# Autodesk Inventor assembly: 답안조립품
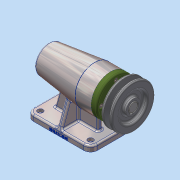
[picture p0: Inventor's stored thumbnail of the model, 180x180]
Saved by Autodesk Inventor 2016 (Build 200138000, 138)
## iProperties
Created: 2018-09
Part Number: 답안조립품
Material: 일반
Document SubType Name: Assembly
Designer: 605-17
Author: 605-17
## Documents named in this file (12)
- C:\Users\605-17\Desktop\480907v1006\답안조립품.iam
- C:\Users\605-17\Desktop\480907v1006\본체.ipt
- C:\Users\605-17\Desktop\480907v1006\축.ipt
- C:\Users\605-17\Desktop\480907v1006\베어링 6004.ipt
- C:\Users\605-17\Desktop\480907v1006\어댑터슬리브.ipt
- C:\Users\605-17\Desktop\480907v1006\베어링 51202.ipt
- C:\Users\605-17\Desktop\480907v1006\볼트 M4.ipt
- C:\Users\605-17\Desktop\480907v1006\키 5 x 5 x 16.ipt
- C:\Users\605-17\Desktop\480907v1006\커버.ipt
- C:\Users\605-17\Desktop\480907v1006\오일 실.ipt
- C:\Users\605-17\Desktop\480907v1006\V벨트풀리.ipt
- C:\Users\605-17\Desktop\480907v1006\멈춤나사 M3.ipt
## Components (1 placed, 1 different names)
1. V벨트풀리:1 — 각도:2
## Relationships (1: Angle 1)
- 각도:2 [Angle]: V벨트풀리:1
